(* Logix 5000 project; controller ASI 1769-L16ER-BB1B rev 32.11; software revision 32.01 *)

TASK MainTask (continuous, watchdog 500 ms) : MainProgram

MODULES
   Local : 1769-L16ER-BB1B (PointIO 0, rev 32.11)
      asigateway : vendor 57 type 12 code 392 (Ethernet 192.168.137.0, rev 2.8, StandardDataDriven RPI 10 ms)
           asigateway:I1.Data[0].4   // F0
           asigateway:I1.Data[0].5   // F1
           asigateway:I1.Data[0].6   // F2
           asigateway:I1.Data[0].7   // F3
           asigateway:I1.Data[17]   // LDS 15-0
           asigateway:I1.Data[21]   // LPS 15-0
           asigateway:I1.Data[25]   // LAS 15-0
           asigateway:I1.Data[29]   // LPF 15-0
           asigateway:I1.Data[2]   // 10A, 11A, 8A, 9A
           asigateway:I1.Data[0]   // 2A, 3A, Flags, 1A
           asigateway:I1.Data[3]   // 14A, 15A, 12A, 13A
           asigateway:I1.Data[4]   // 18A, 19A, 16A, 17A
           asigateway:I1.Data[5]   // 22A, 23A, 20A, 21A
           asigateway:I1.Data[6]   // 26A, 27A, 24A, 25A
           asigateway:I1.Data[7]   // 30A, 31A, 28A, 29A
           asigateway:I1.Data[10]   // 10B, 11B, 8B, 9B
           asigateway:I1.Data[16]   // Diagnostic Bits
           asigateway:I1.Data[16].14   // Power Fail
           asigateway:I1.Data[16].15   // Offline
           asigateway:I1.Data[16].1   // Earth/Ground Fault
           asigateway:I1.Data[16].8   // Configuration Error
           asigateway:I1.Data[16].9   // LDS.0
           asigateway:I1.Data[16].0   // Peripheral Fault
           asigateway:I1.Data[8]   // 2B, 3B, 0, 1B
           asigateway:I1.Data[18]   // LDS 31-16
           asigateway:I1.Data[20]   // LDS 31B-16B
           asigateway:I1.Data[24]   // LPS 31B-16B
           asigateway:I1.Data[19]   // LDS 15B-0
           asigateway:I1.Data[28]   // LAS 31B-16B
           asigateway:I1.Data[32]   // LPF 31B-16B
           asigateway:I1.Data[22]   // LPS 31-16
           asigateway:I1.Data[16].13   // Normal Operation
           asigateway:I1.Data[23]   // LPS 15B-0
           asigateway:I1.Data[26]   // LAS 31-16
           asigateway:I1.Data[1]   // 6A, 7A, 4A, 5A
           asigateway:I1.Data[27]   // LAS 15B-0
           asigateway:I1.Data[9]   // 6B, 7B, 4B, 5B
           asigateway:I1.Data[30]   // LPF 31-16
           asigateway:I1.Data[31]   // LPF 15B-0
           asigateway:I1.Data[11]   // 14B, 15B, 12B, 13B
           asigateway:I1.Data[12]   // 18B, 19B, 16B, 17B
           asigateway:I1.Data[13]   // 22B, 23B, 20B, 21B
           asigateway:I1.Data[14]   // 26B, 27B, 24B, 25B
           asigateway:I1.Data[15]   // 30B, 31B, 28B, 29B
           asigateway:I1.Data[16].10   // Automatic Addressing Not Possible
           asigateway:I1.Data[16].11   // Automatic Addressing Available
           asigateway:I1.Data[16].12   // Configuration Mode Active
           asigateway:I1.Data[33]   // Analog, Adr 27, Channel 1
           asigateway:I1.Data[34]   // Analog, Adr 27, Channel 2
           asigateway:I1.Data[35]   // Analog, Adr 27, Channel 3
           asigateway:I1.Data[36]   // Analog, Adr 27, Channel 4
           asigateway:I1.Data[37]   // Analog, Adr 28, Channel 1
           asigateway:I1.Data[38]   // Analog, Adr 28, Channel 2
           asigateway:I1.Data[39]   // Analog, Adr 28, Channel 3
           asigateway:I1.Data[40]   // Analog, Adr 28, Channel 4
           asigateway:I1.Data[41]   // Analog, Adr 29, Channel 1
           asigateway:I1.Data[42]   // Analog, Adr 29, Channel 2
           asigateway:I1.Data[43]   // Analog, Adr 29, Channel 3
           asigateway:I1.Data[44]   // Analog, Adr 29, Channel 4
           asigateway:I1.Data[45]   // Analog, Adr 30, Channel 1
           asigateway:I1.Data[46]   // Analog, Adr 30, Channel 2
           asigateway:I1.Data[47]   // Analog, Adr 30, Channel 3
           asigateway:I1.Data[48]   // Analog, Adr 30, Channel 4
           asigateway:I1.Data[49]   // Analog, Adr 31, Channel 1
           asigateway:I1.Data[50]   // Analog, Adr 31, Channel 2
           asigateway:I1.Data[51]   // Analog, Adr 31, Channel 3
           asigateway:I1.Data[52]   // Analog, Adr 31, Channel 4
           asigateway:O1.Data[2]   // 10A, 11A, 8A, 9A
           asigateway:O1.Data[3]   // 14A, 15A, 12A, 13A
           asigateway:O1.Data[4]   // 18A, 19A, 16A, 17A
           asigateway:O1.Data[5]   // 22A, 23A, 20A, 21A
           asigateway:O1.Data[6]   // 26A, 27A, 24A, 25A
           asigateway:O1.Data[7]   // 30A, 31A, 28A, 29A
           asigateway:O1.Data[10]   // 10B, 11B, 8B, 9B
           asigateway:O1.Data[0]   // 2A, 3A, 0, 1A
           asigateway:O1.Data[8]   // 2B, 3B, 0, 1B
           asigateway:O1.Data[1]   // 6A, 7A, 4A, 5A
           asigateway:O1.Data[9]   // 6B, 7B, 4B, 5B
           asigateway:O1.Data[14]   // 26B, 27B, 24B, 25B
           asigateway:O1.Data[15]   // 30B, 31B, 28B, 29B
           asigateway:O1.Data[11]   // 14B, 15B, 12B, 13B
           asigateway:O1.Data[12]   // 18B, 19B, 16B, 17B
           asigateway:O1.Data[13]   // 22B, 23B, 20B, 21B
           asigateway:O1.Data[16]   // Analog, Adr 27, Channel 1
           asigateway:O1.Data[17]   // Analog, Adr 27, Channel 2
           asigateway:O1.Data[18]   // Analog, Adr 27, Channel 3
           asigateway:O1.Data[19]   // Analog, Adr 27, Channel 4
           asigateway:O1.Data[20]   // Analog, Adr 28, Channel 1
           asigateway:O1.Data[21]   // Analog, Adr 28, Channel 2
           asigateway:O1.Data[22]   // Analog, Adr 28, Channel 3
           asigateway:O1.Data[23]   // Analog, Adr 28, Channel 4
           asigateway:O1.Data[24]   // Analog, Adr 29, Channel 1
           asigateway:O1.Data[25]   // Analog, Adr 29, Channel 2
           asigateway:O1.Data[26]   // Analog, Adr 29, Channel 3
           asigateway:O1.Data[27]   // Analog, Adr 29, Channel 4
           asigateway:O1.Data[28]   // Analog, Adr 30, Channel 1
           asigateway:O1.Data[29]   // Analog, Adr 30, Channel 2
           asigateway:O1.Data[30]   // Analog, Adr 30, Channel 3
           asigateway:O1.Data[31]   // Analog, Adr 30, Channel 4
           asigateway:O1.Data[32]   // Analog, Adr 31, Channel 1
           asigateway:O1.Data[33]   // Analog, Adr 31, Channel 2
           asigateway:O1.Data[34]   // Analog, Adr 31, Channel 3
           asigateway:O1.Data[35]   // Analog, Adr 31, Channel 4
      Discrete_IO : Embedded (PointIO 1, rev 32.11, Output RPI 20 ms)
END_MODULES

TYPE CTT2Command :
STRUCT
   Address : SINT;   // 1-31=1A-31A or 32-62= 31B-62B
   Command : SINT;   // 18=Read Venddor Specific Object
   Object : SINT;
   Length : SINT;
END_STRUCT
END_TYPE

TYPE Get_Member :
STRUCT
   Address : SINT;   // 1-31 = Address 1A-31A, 32-62 = Address 1B-31B
   Null : SINT;
END_STRUCT
END_TYPE

TYPE PF_Parameters :
STRUCT
   ADR_1A : SINT;
   ADR_2A : SINT;
   ADR_3A : SINT;
   ADR_4A : SINT;
   ADR_5A : SINT;
   ADR_6A : SINT;
   ADR_7A : SINT;
   ADR_8A : SINT;
   ADR_9A : SINT;
   ADR_10A : SINT;
   ADR_11A : SINT;
   ADR_12A : SINT;
   ADR_13A : SINT;
   ADR_14A : SINT;
   ADR_15A : SINT;
   ADR_16A : SINT;
   ADR_17A : SINT;
   ADR_18A : SINT;
   ADR_19A : SINT;
   ADR_20A : SINT;
   ADR_21A : SINT;
   ADR_22A : SINT;
   ADR_23A : SINT;
   ADR_24A : SINT;
   ADR_25A : SINT;
   ADR_26A : SINT;
   ADR_27A : SINT;
   ADR_28A : SINT;
   ADR_29A : SINT;
   ADR_30A : SINT;
   ADR_31A : SINT;
   ADR_1B : SINT;
   ADR_2B : SINT;
   ADR_3B : SINT;
   ADR_4B : SINT;
   ADR_5B : SINT;
   ADR_6B : SINT;
   ADR_7B : SINT;
   ADR_8B : SINT;
   ADR_9B : SINT;
   ADR_10B : SINT;
   ADR_11B : SINT;
   ADR_12B : SINT;
   ADR_13B : SINT;
   ADR_14B : SINT;
   ADR_15B : SINT;
   ADR_16B : SINT;
   ADR_17B : SINT;
   ADR_18B : SINT;
   ADR_19B : SINT;
   ADR_20B : SINT;
   ADR_21B : SINT;
   ADR_22B : SINT;
   ADR_23B : SINT;
   ADR_24B : SINT;
   ADR_25B : SINT;
   ADR_26B : SINT;
   ADR_27B : SINT;
   ADR_28B : SINT;
   ADR_29B : SINT;
   ADR_30B : SINT;
   ADR_31B : SINT;
END_STRUCT
END_TYPE

TYPE PF_Safety_Monitor_Diagnostics :
STRUCT
   NA : SINT;
   NA1 : SINT;
   NA2 : SINT;
   Status : SINT;   // Bit 0=Mode(0-config, 1=protect) Bit 4 Status S12 Bit 5 Status S21 Bit 6 Status S32 Bit 7 Status S41
   OSSD_2_1 : SINT;
   OSSD_4_3 : SINT;
   OSSD_6_5 : SINT;
   OSSD_8_7 : SINT;
   OSSD_10_9 : SINT;
   OSSD_12_11 : SINT;
   OSSD_14_13 : SINT;
   OSSD_16_15 : SINT;
   Device_Index_Present : SINT[32];   // Indexes that are present from 0 to 255
   Device_Index_Color : SINT[128];   // Two Indexes per byte, bits 0-3 device 1, bits 4-7 device 2
END_STRUCT
END_TYPE

TYPE Set_Parameter :
STRUCT
   Address : SINT;   // 1-31=Address 1-31, 32-62=Address 1B-31B
   Parameter : SINT;   // Parameter to Set
END_STRUCT
END_TYPE

TYPE Set_Ramp :
STRUCT
   Address : SINT;   // 1-31=Address 1-31, 32-62=Address 1B-31B
   Ramp : SINT;   // 0=No Ramp, 1=50ms, 2=100ms, 3=200ms, 4=300ms, 5=500ms, 6=1s, 7=1.5s
END_STRUCT
END_TYPE

ADD_ON_INSTRUCTION PF_Safety_Diag_KE5   (* revision 1.0, vendor Pepperl+Fuchs *)
// Reads diagnostics from a safety monitor on a VBg-EP1-KE5...
VAR_INPUT
   Trigger : BOOL; {visible}
   Safety_Monitor_Address : SINT; {visible}   // The address the safety monitor has been set to. Use 0 for Internal safety monitors
   ASi_Network : SINT; {visible}   // Which AS-i network is mailbox command being sent to. 0/1 is network 1, 2 is network 2
   Object : SINT; {visible}
END_VAR
VAR_OUTPUT
   EN : BOOL; {access Read Only, visible}   // Instruction is enabled
   DN : BOOL; {access Read Only, visible}   // DN bit, When on the instruction has completed. Check ER bit for Error
   ER : BOOL; {access Read Only, visible}   // If the DN bit is on and ER bit is off then command was successful. If ER bit is on then check status byte
END_VAR
VAR_IN_OUT
   ReadStringCmdMSG : MESSAGE; {required}
   ReadStringResponseMSG : MESSAGE; {required}
   Source : SINT[4]; {required}
   Destination : SINT[256]; {required}
END_VAR
VAR_OUTPUT
   State_of_OSSD_1 : SINT; {access Read Only, visible}   // 0 Green 1 Green flashing 2 Yellow 3 Yellow flashing 4 Red 5 Red flashing 6 Grey (OSSD not used) 7 Reserved
   State_of_OSSD_2 : SINT; {access Read Only, visible}   // 0 Green 1 Green flashing 2 Yellow 3 Yellow flashing 4 Red 5 Red flashing 6 Grey (OSSD not used) 7 Reserved
   State_of_OSSD_3 : SINT; {access Read Only, visible}   // 0 Green 1 Green flashing 2 Yellow 3 Yellow flashing 4 Red 5 Red flashing 6 Grey (OSSD not used) 7 Reserved
   State_of_OSSD_4 : SINT; {access Read Only, visible}   // 0 Green 1 Green flashing 2 Yellow 3 Yellow flashing 4 Red 5 Red flashing 6 Grey (OSSD not used) 7 Reserved
   State_of_OSSD_5 : SINT; {access Read Only, visible}   // 0 Green 1 Green flashing 2 Yellow 3 Yellow flashing 4 Red 5 Red flashing 6 Grey (OSSD not used) 7 Reserved
   State_of_OSSD_6 : SINT; {access Read Only, visible}   // 0 Green 1 Green flashing 2 Yellow 3 Yellow flashing 4 Red 5 Red flashing 6 Grey (OSSD not used) 7 Reserved
   State_of_OSSD_7 : SINT; {access Read Only, visible}   // 0 Green 1 Green flashing 2 Yellow 3 Yellow flashing 4 Red 5 Red flashing 6 Grey (OSSD not used) 7 Reserved
   State_of_OSSD_8 : SINT; {access Read Only, visible}   // 0 Green 1 Green flashing 2 Yellow 3 Yellow flashing 4 Red 5 Red flashing 6 Grey (OSSD not used) 7 Reserved
   State_of_OSSD_9 : SINT; {access Read Only, visible}   // 0 Green 1 Green flashing 2 Yellow 3 Yellow flashing 4 Red 5 Red flashing 6 Grey (OSSD not used) 7 Reserved
   State_of_OSSD_10 : SINT; {access Read Only, visible}   // 0 Green 1 Green flashing 2 Yellow 3 Yellow flashing 4 Red 5 Red flashing 6 Grey (OSSD not used) 7 Reserved
   State_of_OSSD_11 : SINT; {access Read Only, visible}   // 0 Green 1 Green flashing 2 Yellow 3 Yellow flashing 4 Red 5 Red flashing 6 Grey (OSSD not used) 7 Reserved
   State_of_OSSD_12 : SINT; {access Read Only, visible}   // 0 Green 1 Green flashing 2 Yellow 3 Yellow flashing 4 Red 5 Red flashing 6 Grey (OSSD not used) 7 Reserved
   State_of_OSSD_13 : SINT; {access Read Only, visible}   // 0 Green 1 Green flashing 2 Yellow 3 Yellow flashing 4 Red 5 Red flashing 6 Grey (OSSD not used) 7 Reserved
   State_of_OSSD_14 : SINT; {access Read Only, visible}   // 0 Green 1 Green flashing 2 Yellow 3 Yellow flashing 4 Red 5 Red flashing 6 Grey (OSSD not used) 7 Reserved
   State_of_OSSD_15 : SINT; {access Read Only, visible}   // 0 Green 1 Green flashing 2 Yellow 3 Yellow flashing 4 Red 5 Red flashing 6 Grey (OSSD not used) 7 Reserved
   State_of_OSSD_16 : SINT; {access Read Only, visible}   // 0 Green 1 Green flashing 2 Yellow 3 Yellow flashing 4 Red 5 Red flashing 6 Grey (OSSD not used) 7 Reserved
END_VAR
VAR_IN_OUT
   Device_Presence : SINT[16]; {required}   // 1 bit for each device object used in safety monitor program
   Index_Colors : SINT[128]; {required}   // An array of diagnostic colors 0 Green 1 Green flashing 2 Yellow 3 Yellow flashing 4 Red 5 Red flashing 6 Gray
END_VAR
VAR_OUTPUT
   Last_Index : DINT; {access Read Only, visible}   // The number of diagnostic indexes returned
   Mode : BOOL; {access Read Only, visible}   // Off=Config Mode, On=Protected mode
   S12 : BOOL; {access Read Only, visible}
   S21 : BOOL; {access Read Only, visible}
   S32 : BOOL; {visible}
   S41 : BOOL; {visible}
   Error_Code : INT; {access Read Only, visible}
END_VAR
VAR
   oneshot : DINT; {access None}
   Null : SINT; {access None}
   Indexcolors : DINT; {access None}
   index0 : DINT; {access None}
   index1 : DINT; {access None}
   Color_Pointer : DINT; {access None}
   watchdog : TIMER := (PRE := 8000); {access None}
END_VAR

ROUTINE Logic   (* ladder *)
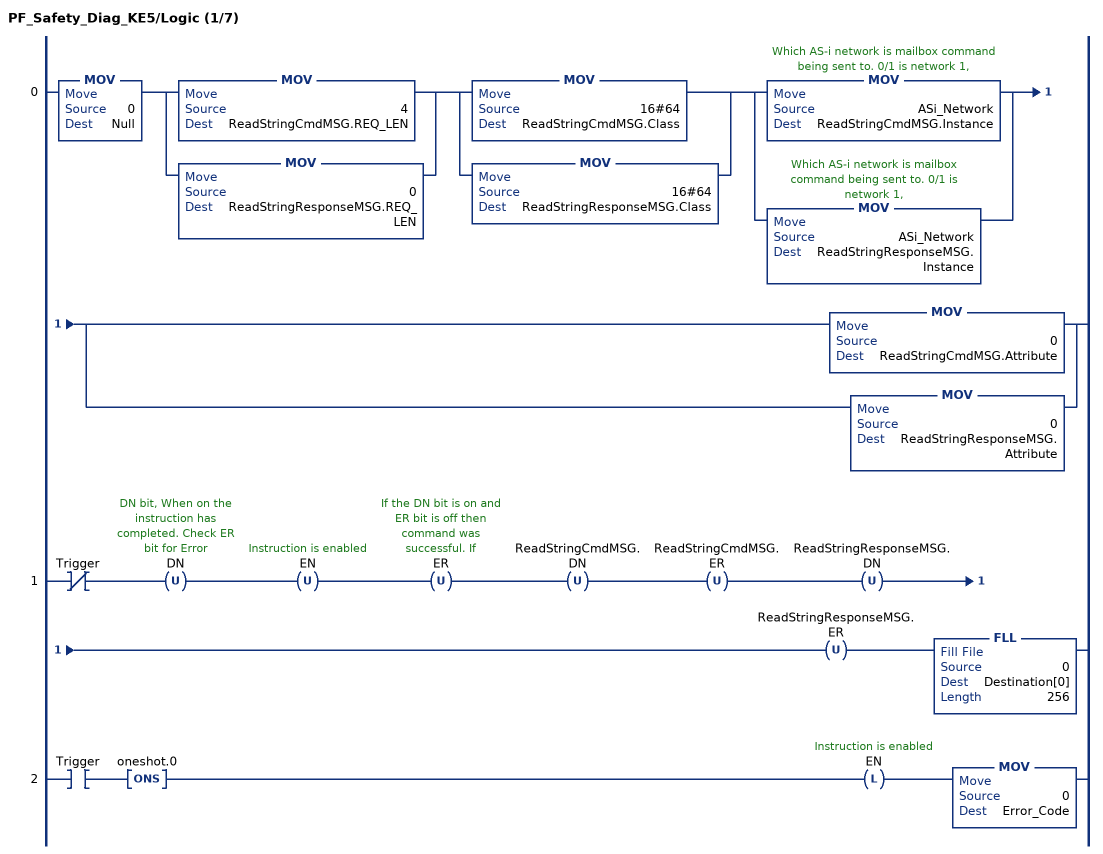
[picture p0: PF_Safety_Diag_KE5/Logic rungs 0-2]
   0: MOV(0,Null)[MOV(4,ReadStringCmdMSG.REQ_LEN) ,MOV(0,ReadStringResponseMSG.REQ_LEN) ][MOV(16#64,ReadStringCmdMSG.Class) ,MOV(16#64,ReadStringResponseMSG.Class) ][MOV(ASi_Network,ReadStringCmdMSG.Instance) ,MOV(ASi_Network,ReadStringResponseMSG.Instance) ][MOV(0,ReadStringCmdMSG.Attribute) ,MOV(0,ReadStringResponseMSG.Attribute) ];
   1: XIO(Trigger)OTU(DN)OTU(EN)OTU(ER)OTU(ReadStringCmdMSG.DN)OTU(ReadStringCmdMSG.ER)OTU(ReadStringResponseMSG.DN)OTU(ReadStringResponseMSG.ER)FLL(0,Destination[0],256);
   2: XIC(Trigger)ONS(oneshot.0)OTL(EN)MOV(0,Error_Code);
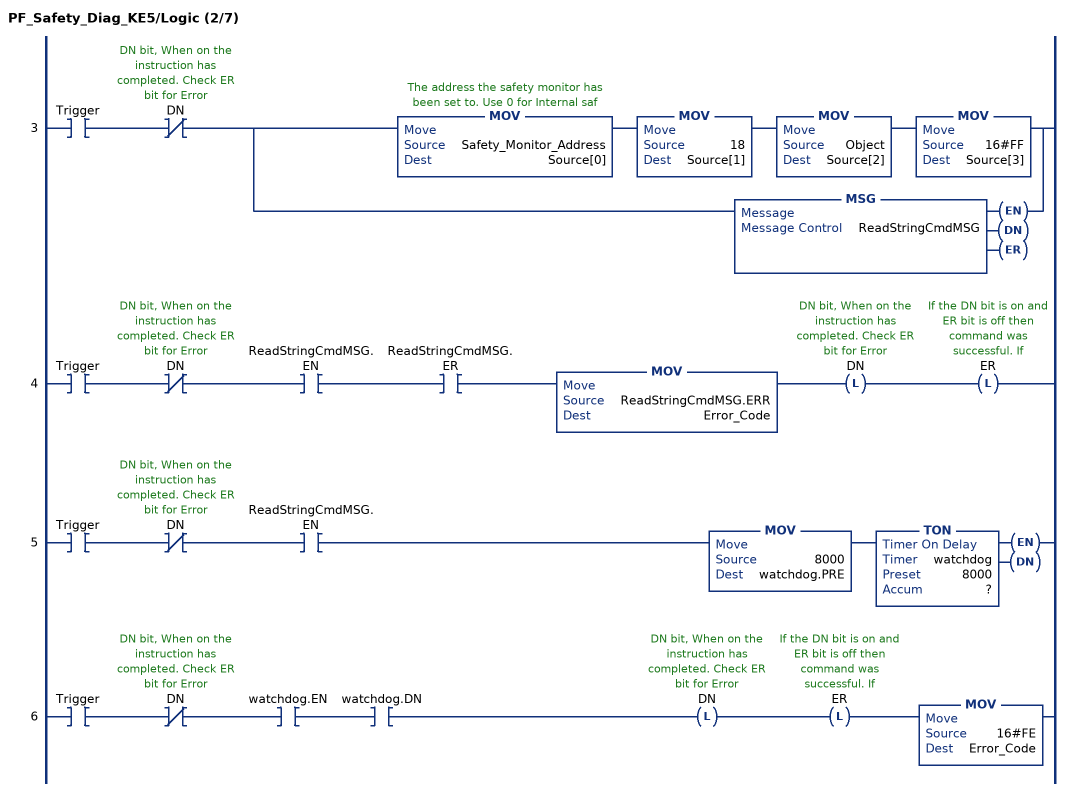
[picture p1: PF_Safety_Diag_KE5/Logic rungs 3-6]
   3: XIC(Trigger)XIO(DN)[MOV(Safety_Monitor_Address,Source[0]) MOV(18,Source[1]) MOV(Object,Source[2]) MOV(16#FF,Source[3]) ,MSG(ReadStringCmdMSG) ];
   4: XIC(Trigger)XIO(DN)XIC(ReadStringCmdMSG.EN)XIC(ReadStringCmdMSG.ER)MOV(ReadStringCmdMSG.ERR,Error_Code)OTL(DN)OTL(ER);
   5: XIC(Trigger)XIO(DN)XIC(ReadStringCmdMSG.EN)MOV(8000,watchdog.PRE)TON(watchdog,?,?);
   6: XIC(Trigger)XIO(DN)XIC(watchdog.EN)XIC(watchdog.DN)OTL(DN)OTL(ER)MOV(16#FE,Error_Code);
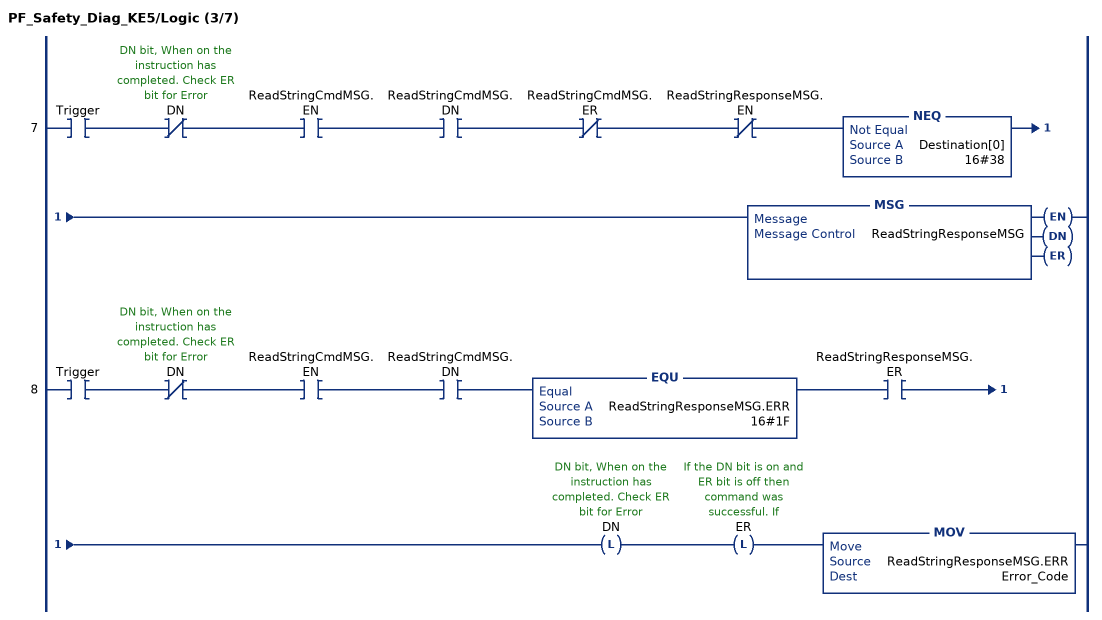
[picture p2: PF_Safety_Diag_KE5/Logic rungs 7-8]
   7: XIC(Trigger)XIO(DN)XIC(ReadStringCmdMSG.EN)XIC(ReadStringCmdMSG.DN)XIO(ReadStringCmdMSG.ER)XIO(ReadStringResponseMSG.EN)NEQ(Destination[0],16#38)MSG(ReadStringResponseMSG);
   8: XIC(Trigger)XIO(DN)XIC(ReadStringCmdMSG.EN)XIC(ReadStringCmdMSG.DN)EQU(ReadStringResponseMSG.ERR,16#1F)XIC(ReadStringResponseMSG.ER)OTL(DN)OTL(ER)MOV(ReadStringResponseMSG.ERR,Error_Code);
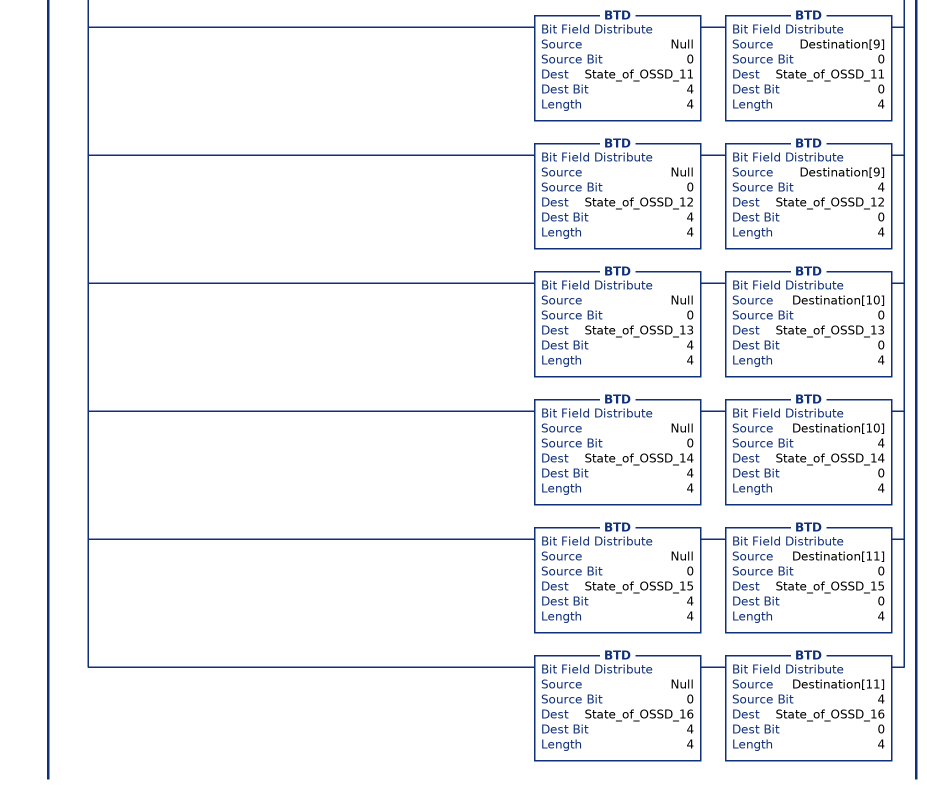
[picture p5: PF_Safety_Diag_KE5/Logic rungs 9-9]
   9: XIC(Trigger)XIO(DN)XIC(ReadStringResponseMSG.DN)XIO(ReadStringResponseMSG.ER)EQU(Destination[0],16#38)ONS(oneshot.2)[[XIC(Destination[3].0) OTL(Mode) ,XIO(Destination[3].0) OTU(Mode) ,XIC(Destination[3].4) OTL(S12) ,XIO(Destination[3].4) OTU(S12) ,XIC(Destination[3].5) OTL(S21) ,XIO(Destination[3].5) OTU(S21) ,XIC(Destination[3].6) OTL(S32) ,XIO(Destination[3].6) OTU(S32) ,XIC(Destination[3].7) OTL(S41) ,XIO(Destination[3].7) OTU(S41) ] ,BTD(Null,0,State_of_OSSD_1,4,4) BTD(Destination[4],0,State_of_OSSD_1,0,4) ,BTD(Null,0,State_of_OSSD_2,4,4) BTD(Destination[4],4,State_of_OSSD_2,0,4) ,BTD(Null,0,State_of_OSSD_3,4,4) BTD(Destination[5],0,State_of_OSSD_3,0,4) ,BTD(Null,0,State_of_OSSD_4,4,4) BTD(Destination[5],4,State_of_OSSD_4,0,4) ,BTD(Null,0,State_of_OSSD_5,4,4) BTD(Destination[6],0,State_of_OSSD_5,0,4) ,BTD(Null,0,State_of_OSSD_6,4,4) BTD(Destination[6],4,State_of_OSSD_6,0,4) ,BTD(Null,0,State_of_OSSD_7,4,4) BTD(Destination[7],0,State_of_OSSD_7,0,4) ,BTD(Null,0,State_of_OSSD_8,4,4) BTD(Destination[7],4,State_of_OSSD_8,0,4) ,BTD(Null,0,State_of_OSSD_9,4,4) BTD(Destination[8],0,State_of_OSSD_9,0,4) ,BTD(Null,0,State_of_OSSD_10,4,4) BTD(Destination[8],4,State_of_OSSD_10,0,4) ,BTD(Null,0,State_of_OSSD_11,4,4) BTD(Destination[9],0,State_of_OSSD_11,0,4) ,BTD(Null,0,State_of_OSSD_12,4,4) BTD(Destination[9],4,State_of_OSSD_12,0,4) ,BTD(Null,0,State_of_OSSD_13,4,4) BTD(Destination[10],0,State_of_OSSD_13,0,4) ,BTD(Null,0,State_of_OSSD_14,4,4) BTD(Destination[10],4,State_of_OSSD_14,0,4) ,BTD(Null,0,State_of_OSSD_15,4,4) BTD(Destination[11],0,State_of_OSSD_15,0,4) ,BTD(Null,0,State_of_OSSD_16,4,4) BTD(Destination[11],4,State_of_OSSD_16,0,4) ];
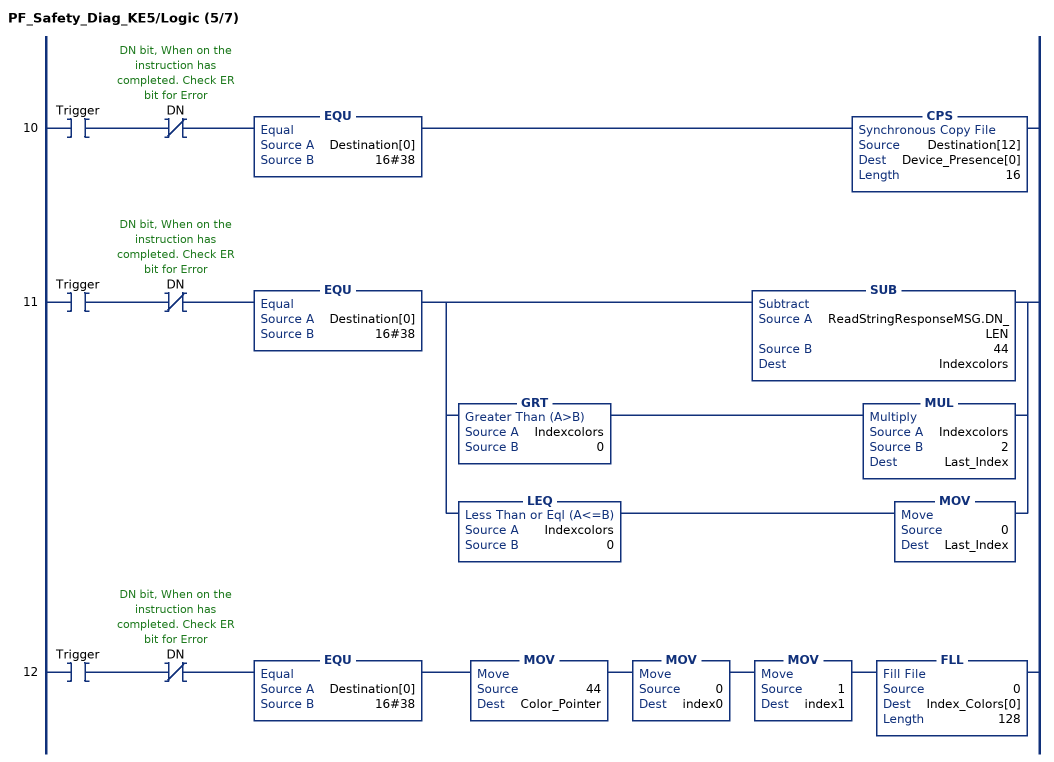
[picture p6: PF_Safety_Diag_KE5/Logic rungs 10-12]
   10: XIC(Trigger)XIO(DN)EQU(Destination[0],16#38)CPS(Destination[12],Device_Presence[0],16);
   11: XIC(Trigger)XIO(DN)EQU(Destination[0],16#38)[SUB(ReadStringResponseMSG.DN_LEN,44,Indexcolors) ,GRT(Indexcolors,0) MUL(Indexcolors,2,Last_Index) ,LEQ(Indexcolors,0) MOV(0,Last_Index) ];
   12: XIC(Trigger)XIO(DN)EQU(Destination[0],16#38)MOV(44,Color_Pointer)MOV(0,index0)MOV(1,index1)FLL(0,Index_Colors[0],128);
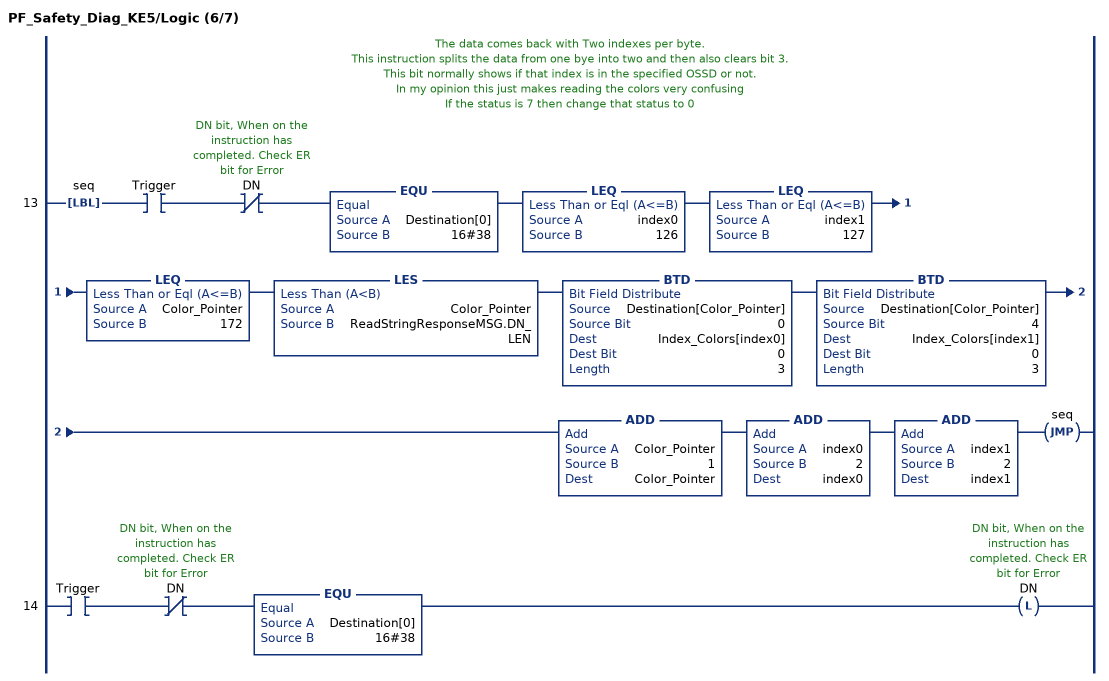
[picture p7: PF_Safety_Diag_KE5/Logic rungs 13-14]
   // The data comes back with Two indexes per byte.
   // This instruction splits the data from one bye into two and then also clears bit 3.
   // This bit normally shows if that index is in the specified OSSD or not.
   // In my opinion this just makes reading the colors very confusing
   // If the status is 7 then change that status to 0
   13: LBL(seq)XIC(Trigger)XIO(DN)EQU(Destination[0],16#38)LEQ(index0,126)LEQ(index1,127)LEQ(Color_Pointer,172)LES(Color_Pointer,ReadStringResponseMSG.DN_LEN)BTD(Destination[Color_Pointer],0,Index_Colors[index0],0,3)BTD(Destination[Color_Pointer],4,Index_Colors[index1],0,3)ADD(Color_Pointer,1,Color_Pointer)ADD(index0,2,index0)ADD(index1,2,index1)JMP(seq);
   14: XIC(Trigger)XIO(DN)EQU(Destination[0],16#38)OTL(DN);
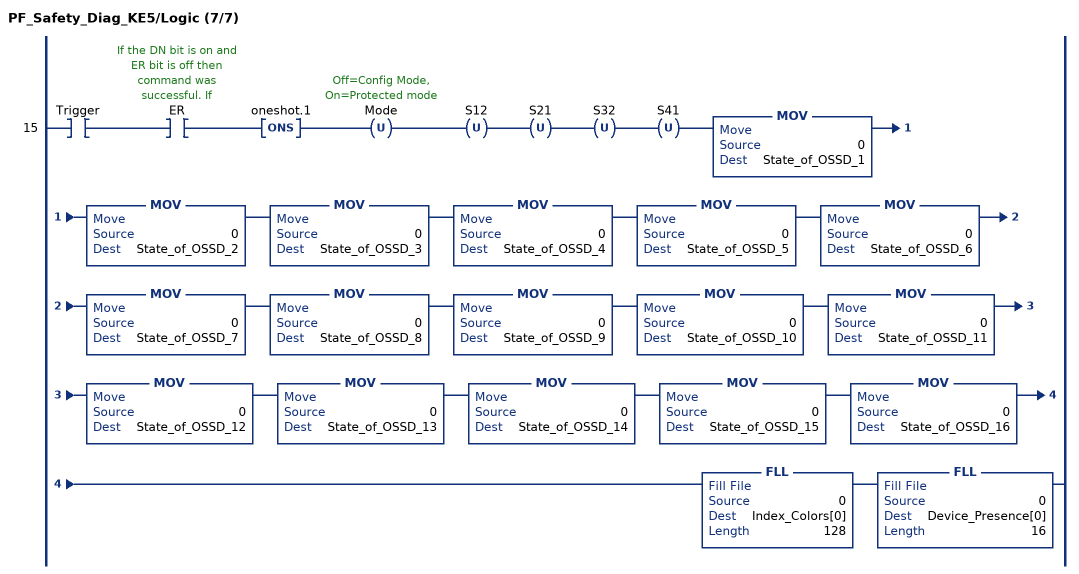
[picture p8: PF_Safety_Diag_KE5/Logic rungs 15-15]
   15: XIC(Trigger)XIC(ER)ONS(oneshot.1)OTU(Mode)OTU(S12)OTU(S21)OTU(S32)OTU(S41)MOV(0,State_of_OSSD_1)MOV(0,State_of_OSSD_2)MOV(0,State_of_OSSD_3)MOV(0,State_of_OSSD_4)MOV(0,State_of_OSSD_5)MOV(0,State_of_OSSD_6)MOV(0,State_of_OSSD_7)MOV(0,State_of_OSSD_8)MOV(0,State_of_OSSD_9)MOV(0,State_of_OSSD_10)MOV(0,State_of_OSSD_11)MOV(0,State_of_OSSD_12)MOV(0,State_of_OSSD_13)MOV(0,State_of_OSSD_14)MOV(0,State_of_OSSD_15)MOV(0,State_of_OSSD_16)FLL(0,Index_Colors[0],128)FLL(0,Device_Presence[0],16);
END_ROUTINE
END_ADD_ON_INSTRUCTION

VAR_GLOBAL   (* controller tags *)
   Actual_Parameter_Return : SINT := 15;
   Actual_Parameters : PF_Parameters;
   Address_1_Running : BOOL := 1;
   colors : SINT[128];
   Command_Status : DINT;
   delaytimer : TIMER := (PRE := 3000);
   Destination : SINT[256];
   device_presence : SINT[16];
   GetResponse : MESSAGE;
        MessageParameters(ServiceCode := 16#0039, DestinationTag := Safety_Monitor, ...)
   Member_of_ASi_Network : Get_Member := (Address := 35);
   MSG_1 : MESSAGE;
        MessageParameters(ServiceCode := 16#000e, DestinationTag := Actual_Parameters, ...)
   MSG_2 : MESSAGE;
        MessageParameters(ServiceCode := 16#0032, LocalElement := Param_Send_Data, DestinationTag := Param_Echo, ...)
   MSG_3 : MESSAGE;
        MessageParameters(ServiceCode := 16#0018, LocalElement := Member_of_ASi_Network, DestinationTag := Actual_Parameter_Return, ...)
   MSG_4 : MESSAGE;
        MessageParameters(ServiceCode := 16#0005, LocalElement := ResetData2, ...)
   MSG_5 : MESSAGE;
        MessageParameters(ServiceCode := 16#000e, DestinationTag := Permanent_Parameters, ...)
   MSG_6 : MESSAGE;
        MessageParameters(ServiceCode := 16#0010, LocalElement := Permanent_Parameters, ...)
   Param_Echo : SINT := 15;
   Param_Send_Data : Set_Parameter := (Address := 1, Parameter := 7);
   Parameters : PF_Parameters;
   Permanent_Parameters : PF_Parameters;
   Read_All_Parameters : BOOL;
   Read_All_Perm_Param : BOOL;
   Read_One_Parameter : BOOL;
   ReadCmdMSG : MESSAGE;
        MessageParameters(ServiceCode := 16#0038, LocalElement := source, DestinationTag := Destination, ...)
   ReadCTT2String : BOOL;
   ReadResponseMSG : MESSAGE;
        MessageParameters(ServiceCode := 16#0039, DestinationTag := Destination, ...)
   ReadSafetyDiagnostics : CTT2Command;
   Reset : BOOL;
   ResetData2 : SINT;
   ResetToggle : BOOL := 1;
   Response : SINT;
   Safety_Monitor : PF_Safety_Monitor_Diagnostics;
   SendCommand : MESSAGE;
        MessageParameters(ServiceCode := 16#0038, LocalElement := ReadSafetyDiagnostics, DestinationTag := Command_Status, ...)
   SetMotorRamp : BOOL;
   SetRampMSG : MESSAGE;
        MessageParameters(ServiceCode := 16#0033, LocalElement := SetRampParameters, DestinationTag := Response, ...)
   SetRampParameters : Set_Ramp;
   source : SINT[4];
   TestKE5Safety : PF_Safety_Diag_KE5 := (Safety_Monitor_Address := 27, ASi_Network := 1, Object := 7);
   Write_All_Perm_Param : BOOL;
   Write_Parameter : BOOL;
END_VAR

PROGRAM MainProgram   (* main routine MainRoutine *)

ROUTINE MainRoutine   (* ladder *)
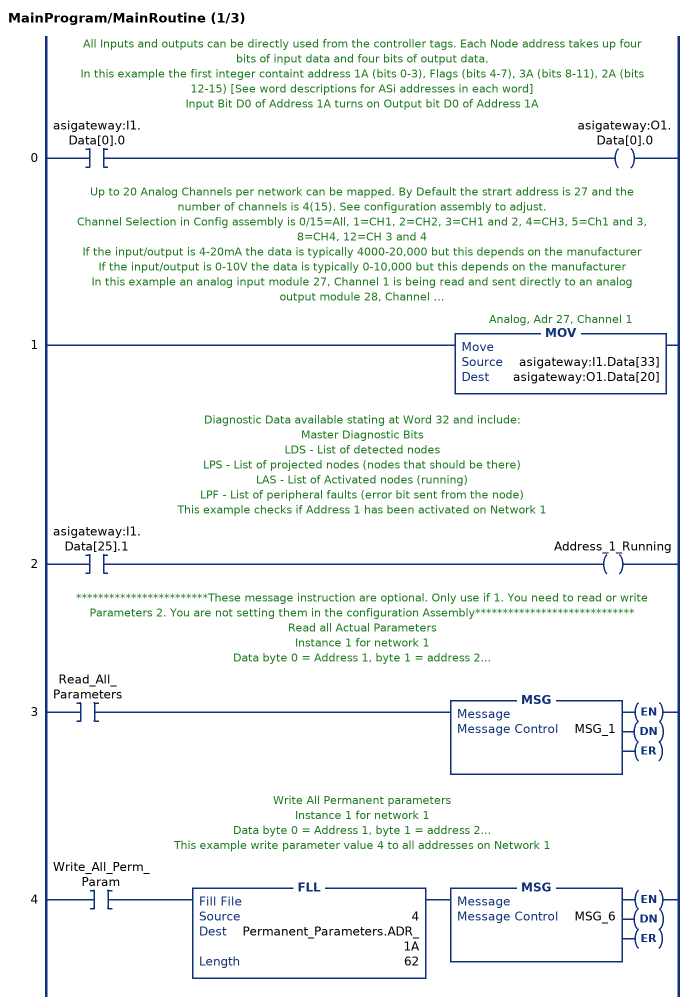
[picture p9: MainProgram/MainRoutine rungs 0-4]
   // All Inputs and outputs can be directly used from the controller tags. Each Node address takes up four bits of input data and four bits of output data.
   // In this example the first integer containt address 1A (bits 0-3), Flags (bits 4-7), 3A (bits 8-11), 2A (bits 12-15) [See word descriptions for ASi addresses in each word]
   // Input Bit D0 of Address 1A turns on Output bit D0 of Address 1A
   0: XIC(asigateway:I1.Data[0].0)OTE(asigateway:O1.Data[0].0);
   // Up to 20 Analog Channels per network can be mapped. By Default the strart address is 27 and the number of channels is 4(15). See configuration assembly to adjust.
   // Channel Selection in Config assembly is 0/15=All, 1=CH1, 2=CH2, 3=CH1 and 2, 4=CH3, 5=Ch1 and 3, 8=CH4, 12=CH 3 and 4
   // If the input/output is 4-20mA the data is typically 4000-20,000 but this depends on the manufacturer
   // If the input/output is 0-10V the data is typically 0-10,000 but this depends on the manufacturer
   // In this example an analog input module 27, Channel 1 is being read and sent directly to an analog output module 28, Channel 1
   // A typical analog module is an input or output module but not both.
   1: MOV(asigateway:I1.Data[33],asigateway:O1.Data[20]);
   // Diagnostic Data available stating at Word 32 and include:
   // Master Diagnostic Bits
   // LDS - List of detected nodes
   // LPS - List of projected nodes (nodes that should be there)
   // LAS - List of Activated nodes (running)
   // LPF - List of peripheral faults (error bit sent from the node)
   // This example checks if Address 1 has been activated on Network 1
   2: XIC(asigateway:I1.Data[25].1)OTE(Address_1_Running);
   // ************************These message instruction are optional. Only use if 1. You need to read or write Parameters 2. You are not setting them in the configuration Assembly*****************************
   // Read all Actual Parameters
   // Instance 1 for network 1
   // Data byte 0 = Address 1, byte 1 = address 2...
   3: XIC(Read_All_Parameters)MSG(MSG_1);
   // Write All Permanent parameters
   // Instance 1 for network 1
   // Data byte 0 = Address 1, byte 1 = address 2...
   // This example write parameter value 4 to all addresses on Network 1
   4: XIC(Write_All_Perm_Param)FLL(4,Permanent_Parameters.ADR_1A,62)MSG(MSG_6);
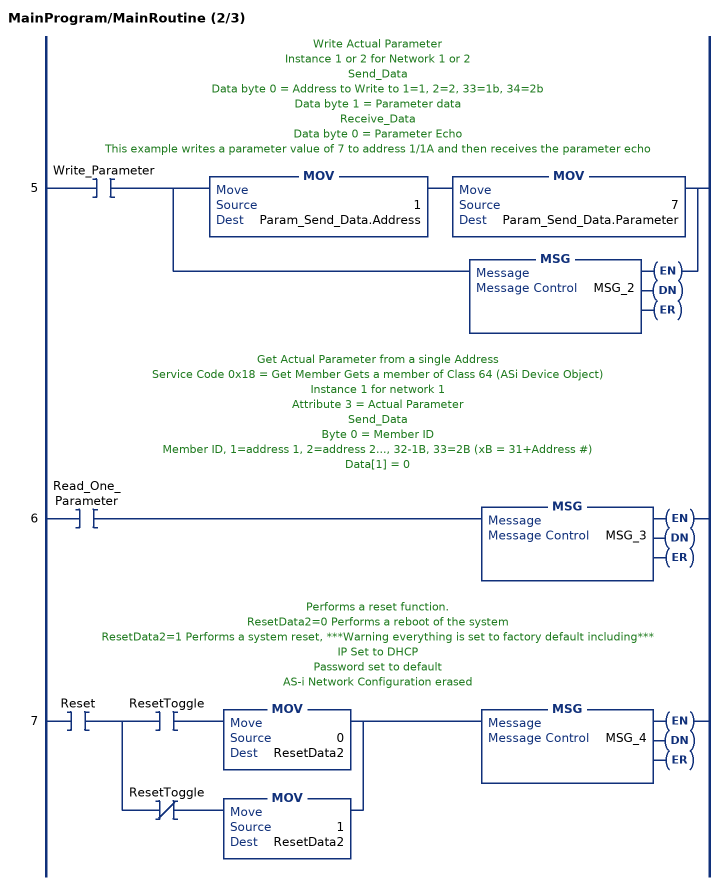
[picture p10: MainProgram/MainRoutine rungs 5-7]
   // Write Actual Parameter
   // Instance 1 or 2 for Network 1 or 2
   // Send_Data
   // Data byte 0 = Address to Write to 1=1, 2=2, 33=1b, 34=2b
   // Data byte 1 = Parameter data
   // Receive_Data
   // Data byte 0 = Parameter Echo
   // This example writes a parameter value of 7 to address 1/1A and then receives the parameter echo
   5: XIC(Write_Parameter)[MOV(1,Param_Send_Data.Address) MOV(7,Param_Send_Data.Parameter) ,MSG(MSG_2) ];
   // Get Actual Parameter from a single Address
   // Service Code 0x18 = Get Member Gets a member of Class 64 (ASi Device Object)
   // Instance 1 for network 1
   // Attribute 3 = Actual Parameter
   // Send_Data
   // Byte 0 = Member ID
   // Member ID, 1=address 1, 2=address 2..., 32-1B, 33=2B (xB = 31+Address #)
   // Data[1] = 0
   6: XIC(Read_One_Parameter)MSG(MSG_3);
   // Performs a reset function.
   // ResetData2=0 Performs a reboot of the system
   // ResetData2=1 Performs a system reset, ***Warning everything is set to factory default including***
   // IP Set to DHCP
   // Password set to default
   // AS-i Network Configuration erased
   7: XIC(Reset)[XIC(ResetToggle) MOV(0,ResetData2) ,XIO(ResetToggle) MOV(1,ResetData2) ]MSG(MSG_4);
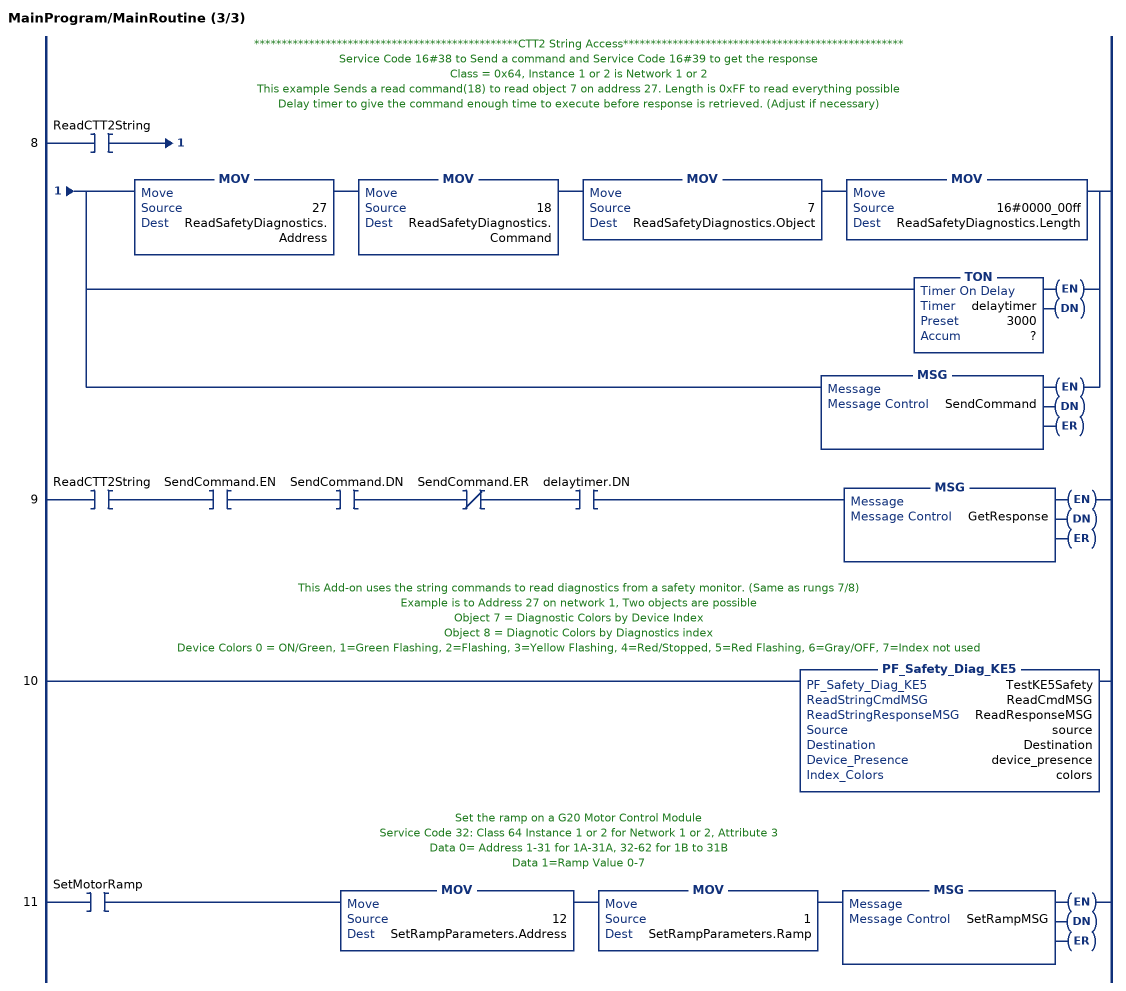
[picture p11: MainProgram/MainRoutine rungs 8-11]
   // ************************************************CTT2 String Access***************************************************
   // Service Code 16#38 to Send a command and Service Code 16#39 to get the response
   // Class = 0x64, Instance 1 or 2 is Network 1 or 2
   // This example Sends a read command(18) to read object 7 on address 27. Length is 0xFF to read everything possible
   // Delay timer to give the command enough time to execute before response is retrieved. (Adjust if necessary)
   8: XIC(ReadCTT2String)[MOV(27,ReadSafetyDiagnostics.Address) MOV(18,ReadSafetyDiagnostics.Command) MOV(7,ReadSafetyDiagnostics.Object) MOV(16#0000_00ff,ReadSafetyDiagnostics.Length) ,TON(delaytimer,?,?) ,MSG(SendCommand) ];
   9: XIC(ReadCTT2String)XIC(SendCommand.EN)XIC(SendCommand.DN)XIO(SendCommand.ER)XIC(delaytimer.DN)MSG(GetResponse);
   // This Add-on uses the string commands to read diagnostics from a safety monitor. (Same as rungs 7/8)
   // Example is to Address 27 on network 1, Two objects are possible
   // Object 7 = Diagnostic Colors by Device Index
   // Object 8 = Diagnotic Colors by Diagnostics index
   // Device Colors 0 = ON/Green, 1=Green Flashing, 2=Flashing, 3=Yellow Flashing, 4=Red/Stopped, 5=Red Flashing, 6=Gray/OFF, 7=Index not used
   10: PF_Safety_Diag_KE5(TestKE5Safety,ReadCmdMSG,ReadResponseMSG,source,Destination,device_presence,colors);
   // Set the ramp on a G20 Motor Control Module
   // Service Code 32: Class 64 Instance 1 or 2 for Network 1 or 2, Attribute 3
   // Data 0= Address 1-31 for 1A-31A, 32-62 for 1B to 31B
   // Data 1=Ramp Value 0-7
   11: XIC(SetMotorRamp)MOV(12,SetRampParameters.Address)MOV(1,SetRampParameters.Ramp)MSG(SetRampMSG);
END_ROUTINE
END_PROGRAM
